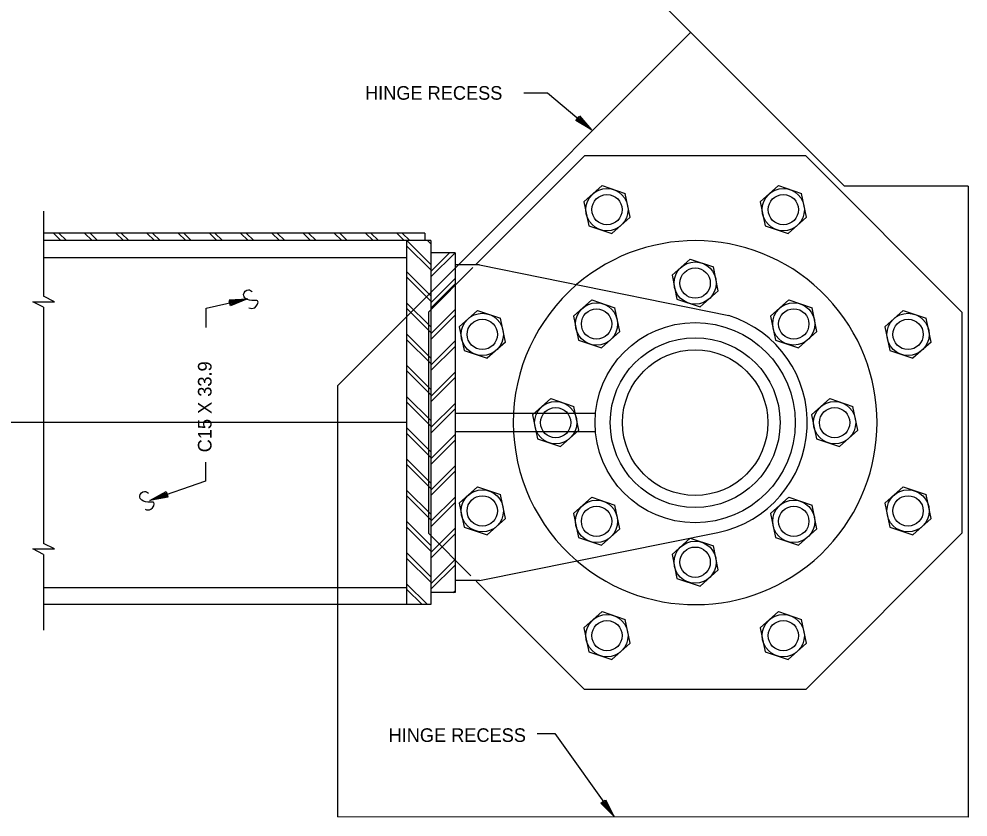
# Model space of a CAD drawing. Extents: x -0.2 to 13.5, y -0.2 to 9.5.
# Drawn here: x 6.602 to 9.863, y 4.919 to 7.66 of the extents above; entities that cross this region are included whole.
import ezdxf

# ---------------------------------------------------------------- set-up
doc = ezdxf.new("R2010")
doc.units = 0
for name, color, linetype in [('Level 13', 7, 'Continuous'), ('Level 2', 7, 'Continuous'), ('Level 25', 7, 'Continuous'), ('Level 3', 7, 'Continuous')]:
    doc.layers.add(name, color=color, linetype=linetype)

msp = doc.modelspace()

# ---------------------------------------------------------------- linework, layer by layer
at = {"layer": 'Level 13'}
for p, q in [((8.5428, 7.0317), (8.6056, 7.0874)), ((8.5428, 7.0317), (8.6056, 7.0874)), ((8.6056, 7.0874), (8.6849, 7.061)), ((8.6056, 7.0874), (8.6849, 7.061)), ((9.1487, 7.0317), (9.2116, 7.0874)), ((9.1487, 7.0317), (9.2116, 7.0874)), ((9.2116, 7.0874), (9.2908, 7.061)), ((9.2116, 7.0874), (9.2908, 7.061)), ((8.7018, 6.9787), (8.6849, 7.061)), ((8.7018, 6.9787), (8.6849, 7.061)), ((9.3077, 6.9787), (9.2908, 7.061)), ((9.3077, 6.9787), (9.2908, 7.061)), ((8.5428, 7.0317), (8.5596, 6.9494)), ((8.5428, 7.0317), (8.5596, 6.9494)), ((9.1487, 7.0317), (9.1656, 6.9494)), ((9.1487, 7.0317), (9.1656, 6.9494)), ((8.7018, 6.9787), (8.6389, 6.923)), ((8.7018, 6.9787), (8.6389, 6.923)), ((9.3077, 6.9787), (9.2448, 6.923)), ((9.3077, 6.9787), (9.2448, 6.923)), ((8.5596, 6.9494), (8.6389, 6.923)), ((8.5596, 6.9494), (8.6389, 6.923)), ((9.1656, 6.9494), (9.2448, 6.923)), ((9.1656, 6.9494), (9.2448, 6.923)), ((8.8458, 6.7795), (8.9086, 6.8352)), ((8.8458, 6.7795), (8.9086, 6.8352)), ((8.9086, 6.8352), (8.9879, 6.8088)), ((8.9086, 6.8352), (8.9879, 6.8088)), ((9.0047, 6.7265), (8.9879, 6.8088)), ((9.0047, 6.7265), (8.9879, 6.8088)), ((8.8458, 6.7795), (8.8626, 6.6972)), ((8.8458, 6.7795), (8.8626, 6.6972)), ((9.0047, 6.7265), (8.9419, 6.6708)), ((9.0047, 6.7265), (8.9419, 6.6708)), ((8.5069, 6.6391), (8.5698, 6.6948)), ((8.5069, 6.6391), (8.5698, 6.6948)), ((8.5698, 6.6948), (8.6491, 6.6684)), ((8.5698, 6.6948), (8.6491, 6.6684)), ((8.8626, 6.6972), (8.9419, 6.6708)), ((8.8626, 6.6972), (8.9419, 6.6708)), ((9.1846, 6.6391), (9.2474, 6.6948)), ((9.1846, 6.6391), (9.2474, 6.6948)), ((9.2474, 6.6948), (9.3267, 6.6684)), ((9.2474, 6.6948), (9.3267, 6.6684)), ((8.1143, 6.6032), (8.1772, 6.659)), ((8.1143, 6.6032), (8.1772, 6.659)), ((8.1772, 6.659), (8.2565, 6.6325)), ((8.1772, 6.659), (8.2565, 6.6325)), ((8.6659, 6.5861), (8.6491, 6.6684)), ((8.6659, 6.5861), (8.6491, 6.6684)), ((9.3436, 6.5861), (9.3267, 6.6684)), ((9.3436, 6.5861), (9.3267, 6.6684)), ((9.5771, 6.6032), (9.64, 6.659)), ((9.5771, 6.6032), (9.64, 6.659)), ((9.64, 6.659), (9.7193, 6.6325)), ((9.64, 6.659), (9.7193, 6.6325)), ((8.2733, 6.5502), (8.2565, 6.6325)), ((8.2733, 6.5502), (8.2565, 6.6325)), ((8.5069, 6.6391), (8.5238, 6.5568)), ((8.5069, 6.6391), (8.5238, 6.5568)), ((9.1846, 6.6391), (9.2014, 6.5569)), ((9.1846, 6.6391), (9.2014, 6.5569)), ((9.7361, 6.5502), (9.7193, 6.6325)), ((9.7361, 6.5502), (9.7193, 6.6325)), ((8.1143, 6.6032), (8.1312, 6.521)), ((8.1143, 6.6032), (8.1312, 6.521)), ((9.5771, 6.6032), (9.594, 6.521)), ((9.5771, 6.6032), (9.594, 6.521)), ((8.5238, 6.5568), (8.6031, 6.5304)), ((8.5238, 6.5568), (8.6031, 6.5304)), ((8.6659, 6.5861), (8.6031, 6.5304)), ((8.6659, 6.5861), (8.6031, 6.5304)), ((9.2014, 6.5569), (9.2807, 6.5304)), ((9.2014, 6.5569), (9.2807, 6.5304)), ((9.3436, 6.5861), (9.2807, 6.5304)), ((9.3436, 6.5861), (9.2807, 6.5304)), ((8.2733, 6.5502), (8.2105, 6.4945)), ((8.2733, 6.5502), (8.2105, 6.4945)), ((9.7361, 6.5502), (9.6733, 6.4945)), ((9.7361, 6.5502), (9.6733, 6.4945)), ((8.1312, 6.521), (8.2105, 6.4945)), ((8.1312, 6.521), (8.2105, 6.4945)), ((9.594, 6.521), (9.6733, 6.4945)), ((9.594, 6.521), (9.6733, 6.4945)), ((8.3666, 6.3003), (8.4294, 6.356)), ((8.3666, 6.3003), (8.4294, 6.356)), ((8.4294, 6.356), (8.5087, 6.3296)), ((8.4294, 6.356), (8.5087, 6.3296)), ((8.5256, 6.2473), (8.5087, 6.3296)), ((8.5256, 6.2473), (8.5087, 6.3296)), ((9.3249, 6.3003), (9.3878, 6.356)), ((9.3249, 6.3003), (9.3878, 6.356)), ((9.3878, 6.356), (9.4671, 6.3296)), ((9.3878, 6.356), (9.4671, 6.3296)), ((9.4839, 6.2473), (9.4671, 6.3296)), ((9.4839, 6.2473), (9.4671, 6.3296)), ((8.3666, 6.3003), (8.3834, 6.218)), ((8.3666, 6.3003), (8.3834, 6.218)), ((9.3249, 6.3003), (9.3418, 6.218)), ((9.3249, 6.3003), (9.3418, 6.218)), ((8.5256, 6.2473), (8.4627, 6.1916)), ((8.5256, 6.2473), (8.4627, 6.1916)), ((9.4839, 6.2473), (9.4211, 6.1916)), ((9.4839, 6.2473), (9.4211, 6.1916)), ((8.3834, 6.218), (8.4627, 6.1916)), ((8.3834, 6.218), (8.4627, 6.1916)), ((9.3418, 6.218), (9.4211, 6.1916)), ((9.3418, 6.218), (9.4211, 6.1916)), ((8.1143, 5.9973), (8.1772, 6.0531)), ((8.1143, 5.9973), (8.1772, 6.0531)), ((8.1772, 6.0531), (8.2565, 6.0266)), ((8.1772, 6.0531), (8.2565, 6.0266)), ((9.5771, 5.9973), (9.64, 6.0531)), ((9.5771, 5.9973), (9.64, 6.0531)), ((9.64, 6.0531), (9.7193, 6.0266)), ((9.64, 6.0531), (9.7193, 6.0266)), ((8.2733, 5.9443), (8.2565, 6.0266)), ((8.2733, 5.9443), (8.2565, 6.0266)), ((8.5069, 5.9615), (8.5698, 6.0172)), ((8.5069, 5.9615), (8.5698, 6.0172)), ((8.5698, 6.0172), (8.6491, 5.9908)), ((8.5698, 6.0172), (8.6491, 5.9908)), ((9.1846, 5.9615), (9.2474, 6.0172)), ((9.1846, 5.9615), (9.2474, 6.0172)), ((9.2474, 6.0172), (9.3267, 5.9908)), ((9.2474, 6.0172), (9.3267, 5.9908)), ((9.7361, 5.9443), (9.7193, 6.0266)), ((9.7361, 5.9443), (9.7193, 6.0266)), ((8.1143, 5.9973), (8.1312, 5.9151)), ((8.1143, 5.9973), (8.1312, 5.9151)), ((8.6659, 5.9085), (8.6491, 5.9908)), ((8.6659, 5.9085), (8.6491, 5.9908)), ((9.3435, 5.9085), (9.3267, 5.9908)), ((9.3435, 5.9085), (9.3267, 5.9908)), ((9.5771, 5.9973), (9.594, 5.9151)), ((9.5771, 5.9973), (9.594, 5.9151)), ((8.2733, 5.9443), (8.2105, 5.8886)), ((8.2733, 5.9443), (8.2105, 5.8886)), ((8.5069, 5.9615), (8.5238, 5.8792)), ((8.5069, 5.9615), (8.5238, 5.8792)), ((9.1846, 5.9615), (9.2014, 5.8792)), ((9.1846, 5.9615), (9.2014, 5.8792)), ((9.7361, 5.9443), (9.6733, 5.8886)), ((9.7361, 5.9443), (9.6733, 5.8886)), ((8.1312, 5.9151), (8.2105, 5.8886)), ((8.1312, 5.9151), (8.2105, 5.8886)), ((8.6659, 5.9085), (8.6031, 5.8528)), ((8.6659, 5.9085), (8.6031, 5.8528)), ((9.3435, 5.9085), (9.2807, 5.8528)), ((9.3435, 5.9085), (9.2807, 5.8528)), ((9.594, 5.9151), (9.6733, 5.8886)), ((9.594, 5.9151), (9.6733, 5.8886)), ((8.5238, 5.8792), (8.6031, 5.8528)), ((8.5238, 5.8792), (8.6031, 5.8528)), ((8.8458, 5.8211), (8.9086, 5.8769)), ((8.8458, 5.8211), (8.9086, 5.8769)), ((8.9086, 5.8769), (8.9879, 5.8504)), ((8.9086, 5.8769), (8.9879, 5.8504)), ((9.2014, 5.8792), (9.2807, 5.8528)), ((9.2014, 5.8792), (9.2807, 5.8528)), ((9.0047, 5.7681), (8.9879, 5.8504)), ((9.0047, 5.7681), (8.9879, 5.8504)), ((8.8458, 5.8211), (8.8626, 5.7389)), ((8.8458, 5.8211), (8.8626, 5.7389)), ((9.0047, 5.7681), (8.9419, 5.7124)), ((9.0047, 5.7681), (8.9419, 5.7124)), ((8.8626, 5.7389), (8.9419, 5.7124)), ((8.8626, 5.7389), (8.9419, 5.7124)), ((8.5428, 5.5689), (8.6056, 5.6246)), ((8.5428, 5.5689), (8.6056, 5.6246)), ((8.6056, 5.6246), (8.6849, 5.5982)), ((8.6056, 5.6246), (8.6849, 5.5982)), ((9.1487, 5.5689), (9.2115, 5.6246)), ((9.1487, 5.5689), (9.2115, 5.6246)), ((9.2115, 5.6246), (9.2908, 5.5982)), ((9.2115, 5.6246), (9.2908, 5.5982)), ((8.7018, 5.5159), (8.6849, 5.5982)), ((8.7018, 5.5159), (8.6849, 5.5982)), ((9.3077, 5.5159), (9.2908, 5.5982)), ((9.3077, 5.5159), (9.2908, 5.5982)), ((8.5428, 5.5689), (8.5596, 5.4866)), ((8.5428, 5.5689), (8.5596, 5.4866)), ((9.1487, 5.5689), (9.1655, 5.4866)), ((9.1487, 5.5689), (9.1655, 5.4866)), ((8.7018, 5.5159), (8.6389, 5.4602)), ((8.7018, 5.5159), (8.6389, 5.4602)), ((9.3077, 5.5159), (9.2448, 5.4602)), ((9.3077, 5.5159), (9.2448, 5.4602)), ((8.5596, 5.4866), (8.6389, 5.4602)), ((8.5596, 5.4866), (8.6389, 5.4602)), ((9.1655, 5.4866), (9.2448, 5.4602)), ((9.1655, 5.4866), (9.2448, 5.4602))]:
    msp.add_line(p, q, dxfattribs=at)
for points in [[(6.6867, 6.6703), (6.6492, 6.6889), (6.7241, 6.6889), (6.6867, 6.7077)], [(6.6867, 5.8214), (6.6492, 5.8401), (6.7241, 5.8401), (6.6867, 5.8588)]]:
    msp.add_lwpolyline(points, dxfattribs=at)
for centre in [(8.6222, 7.005), (8.6222, 7.005), (9.2281, 7.005), (9.2281, 7.005), (8.9252, 6.7528), (8.9252, 6.7528), (8.5864, 6.6124), (8.5864, 6.6124), (9.264, 6.6125), (9.264, 6.6125), (8.1938, 6.5766), (8.1938, 6.5766), (9.6566, 6.5766), (9.6566, 6.5766), (8.446, 6.2736), (8.446, 6.2736), (9.4044, 6.2736), (9.4044, 6.2736), (8.1938, 5.9707), (8.1938, 5.9707), (9.6566, 5.9707), (9.6566, 5.9707), (8.5864, 5.9348), (8.5864, 5.9348), (9.264, 5.9348), (9.264, 5.9348), (8.9252, 5.7945), (8.9252, 5.7945), (8.6222, 5.5422), (8.6222, 5.5422), (9.2281, 5.5422), (9.2281, 5.5422)]:
    msp.add_circle(centre, 0.0725, dxfattribs=at)
at = {"layer": 'Level 2'}
for p, q in [((6.746, 6.8986), (6.72, 6.9247)), ((6.7649, 6.8986), (6.7388, 6.9247)), ((6.8533, 6.8986), (6.8272, 6.9247)), ((6.8721, 6.8986), (6.8461, 6.9247)), ((6.9605, 6.8986), (6.9345, 6.9247)), ((6.9794, 6.8986), (6.9533, 6.9247)), ((7.0678, 6.8986), (7.0417, 6.9247)), ((7.0866, 6.8986), (7.0606, 6.9247)), ((7.175, 6.8986), (7.1489, 6.9247)), ((7.1938, 6.8986), (7.1678, 6.9247)), ((7.2822, 6.8986), (7.2562, 6.9247)), ((7.3011, 6.8986), (7.2751, 6.9247)), ((7.3895, 6.8986), (7.3634, 6.9247)), ((7.4083, 6.8986), (7.3823, 6.9247)), ((7.4967, 6.8986), (7.4707, 6.9247)), ((7.5156, 6.8986), (7.4895, 6.9247)), ((7.604, 6.8986), (7.5779, 6.9247)), ((7.6228, 6.8986), (7.5968, 6.9247)), ((7.7112, 6.8986), (7.6852, 6.9247)), ((7.7301, 6.8986), (7.704, 6.9247)), ((7.8185, 6.8986), (7.7924, 6.9247)), ((7.8373, 6.8986), (7.8113, 6.9247)), ((7.9257, 6.8986), (7.8997, 6.9247)), ((7.9446, 6.8986), (7.9185, 6.9247)), ((8.0171, 6.8168), (7.9337, 6.9001)), ((8.0171, 6.7979), (7.9337, 6.8812)), ((8.0171, 6.8874), (8.0058, 6.8986)), ((8.0171, 6.7739), (8.1001, 6.857)), ((8.0171, 6.7928), (8.0813, 6.857)), ((6.6867, 6.8402), (7.9337, 6.8402)), ((8.0171, 6.7095), (7.9337, 6.7928)), ((8.1004, 6.8041), (8.1004, 6.8041)), ((8.0171, 6.6906), (7.9337, 6.774)), ((8.0171, 6.6855), (8.1004, 6.7688)), ((8.0171, 6.6666), (8.1004, 6.75)), ((8.0171, 6.6023), (7.9337, 6.6856)), ((8.0171, 6.5834), (7.9337, 6.6667)), ((8.0171, 6.5783), (8.1004, 6.6616)), ((8.0171, 6.5594), (8.1004, 6.6427)), ((8.0171, 6.495), (7.9337, 6.5783)), ((8.0171, 6.4762), (7.9337, 6.5595)), ((8.0171, 6.471), (8.1004, 6.5543)), ((8.0171, 6.4522), (8.1004, 6.5355)), ((8.0171, 6.3878), (7.9337, 6.4711)), ((8.0171, 6.3689), (7.9337, 6.4523)), ((8.0171, 6.3638), (8.1004, 6.4471)), ((8.0171, 6.3449), (8.1004, 6.4282)), ((8.0171, 6.2805), (7.9337, 6.3639)), ((8.0171, 6.2617), (7.9337, 6.345)), ((8.0171, 6.2565), (8.1004, 6.3398)), ((8.0171, 6.2377), (8.1004, 6.321)), ((7.9337, 6.2736), (6.0129, 6.2736)), ((8.0171, 6.1733), (7.9337, 6.2566)), ((8.0171, 6.1544), (7.9337, 6.2378)), ((8.0171, 6.1493), (8.1004, 6.2326)), ((8.0171, 6.1304), (8.1004, 6.2137)), ((8.0171, 6.066), (7.9337, 6.1494)), ((8.0171, 6.0472), (7.9337, 6.1305)), ((8.0171, 6.042), (8.1004, 6.1253)), ((8.0171, 6.0232), (8.1004, 6.1065)), ((8.0171, 5.9588), (7.9337, 6.0421)), ((8.0171, 5.9399), (7.9337, 6.0233)), ((8.0171, 5.9348), (8.1004, 6.0181)), ((8.0171, 5.9159), (8.1004, 5.9993)), ((8.0171, 5.8516), (7.9337, 5.9349)), ((8.0171, 5.8327), (7.9337, 5.916)), ((8.0171, 5.8275), (8.1004, 5.9109)), ((8.0171, 5.8087), (8.1004, 5.892)), ((8.0171, 5.7443), (7.9337, 5.8276)), ((8.0171, 5.7254), (7.9337, 5.8088)), ((8.0171, 5.7203), (8.1004, 5.8036)), ((8.0171, 5.7014), (8.1004, 5.7848)), ((6.6867, 5.707), (7.9337, 5.707)), ((8.0055, 5.6486), (7.9337, 5.7204)), ((7.9867, 5.6486), (7.9337, 5.7015)), ((8.0943, 5.6903), (8.1004, 5.6964))]:
    msp.add_line(p, q, dxfattribs=at)
at = {"layer": 'Level 25'}
for p, q in [((8.4318, 8.0929), (9.4385, 7.0861)), ((8.9105, 7.6142), (8.1004, 6.8041)), ((8.5455, 7.1903), (8.1727, 6.8175)), ((8.5455, 7.1903), (8.1727, 6.8175)), ((9.3049, 7.1903), (8.5455, 7.1903)), ((9.3049, 7.1903), (8.5455, 7.1903)), ((9.3049, 7.1903), (9.8419, 6.6533)), ((9.3049, 7.1903), (9.8419, 6.6533)), ((9.8627, 7.0861), (9.4385, 7.0861)), ((9.8627, 7.0861), (9.8627, 4.9194)), ((6.6867, 6.9996), (6.6867, 6.7077)), ((7.9962, 6.9247), (6.6867, 6.9247)), ((7.9962, 6.9247), (6.6867, 6.9247)), ((7.9962, 6.9247), (7.9962, 6.8986)), ((7.9962, 6.9247), (7.9962, 6.8986)), ((8.0171, 6.8986), (6.6867, 6.8986)), ((8.0171, 6.8986), (6.6867, 6.8986)), ((7.9337, 6.8986), (7.9337, 5.6486)), ((8.0171, 6.8986), (8.0171, 5.6486)), ((8.1004, 6.857), (8.0171, 6.857)), ((8.1004, 6.857), (8.0171, 6.857)), ((8.1004, 6.857), (8.1004, 5.6903)), ((8.1004, 6.857), (8.1004, 5.6903)), ((8.1837, 6.8153), (8.1004, 6.8153)), ((8.1837, 6.8153), (8.1004, 6.8153)), ((8.1837, 6.8153), (9.041, 6.6413)), ((8.1837, 6.8153), (9.041, 6.6413)), ((8.1004, 6.8041), (7.696, 6.3998)), ((8.1611, 6.8059), (8.0085, 6.6533)), ((8.1611, 6.8059), (8.0085, 6.6533)), ((6.6867, 6.6703), (6.6867, 5.8588)), ((6.6867, 6.6703), (6.6867, 5.9392)), ((8.0085, 6.6533), (8.0085, 5.894)), ((8.0085, 6.6533), (8.0085, 5.894)), ((8.0085, 6.6533), (8.0085, 5.894)), ((9.8419, 6.6533), (9.8419, 5.8939)), ((9.8419, 6.6533), (9.8419, 5.8939)), ((7.696, 6.3998), (7.696, 5.6486)), ((8.5829, 6.3049), (8.1004, 6.3049)), ((8.5829, 6.3049), (8.1004, 6.3049)), ((8.5829, 6.2424), (8.1004, 6.2424)), ((8.5829, 6.2424), (8.1004, 6.2424)), ((8.0085, 5.8939), (8.1545, 5.7479)), ((8.0085, 5.8939), (8.1545, 5.7479)), ((8.1837, 5.732), (9.0033, 5.8962)), ((8.1837, 5.732), (9.0033, 5.8962)), ((9.8419, 5.8939), (9.3049, 5.357)), ((9.8419, 5.8939), (9.3049, 5.357)), ((6.6867, 5.8214), (6.6867, 5.5605)), ((8.1837, 5.732), (8.1004, 5.732)), ((8.1837, 5.732), (8.1004, 5.732)), ((8.1727, 5.7298), (8.5455, 5.357)), ((8.1727, 5.7298), (8.5455, 5.357)), ((8.1004, 5.6903), (8.0171, 5.6903)), ((8.1004, 5.6903), (8.0171, 5.6903)), ((8.0171, 5.6486), (6.6867, 5.6486)), ((7.696, 5.6486), (7.696, 4.9195)), ((9.3049, 5.357), (8.5455, 5.357)), ((9.3049, 5.357), (8.5455, 5.357)), ((9.8627, 4.9194), (7.696, 4.9195))]:
    msp.add_line(p, q, dxfattribs=at)
for centre, radius in [((8.6222, 7.005), 0.0521), ((8.6222, 7.005), 0.0521), ((9.2281, 7.005), 0.0521), ((9.2281, 7.005), 0.0521), ((8.9252, 6.7528), 0.0521), ((8.9252, 6.7528), 0.0521), ((8.5864, 6.6124), 0.0521), ((8.5864, 6.6124), 0.0521), ((9.264, 6.6125), 0.0521), ((9.264, 6.6125), 0.0521), ((8.1938, 6.5766), 0.0521), ((8.1938, 6.5766), 0.0521), ((9.6566, 6.5766), 0.0521), ((9.6566, 6.5766), 0.0521), ((8.9252, 6.2736), 0.3438), ((8.9252, 6.2736), 0.3438), ((8.9252, 6.2736), 0.2917), ((8.9252, 6.2736), 0.2917), ((8.9252, 6.2736), 0.25), ((8.9252, 6.2736), 0.25), ((8.446, 6.2736), 0.0521), ((8.446, 6.2736), 0.0521), ((9.4044, 6.2736), 0.0521), ((9.4044, 6.2736), 0.0521), ((8.1938, 5.9707), 0.0521), ((8.1938, 5.9707), 0.0521), ((9.6566, 5.9707), 0.0521), ((9.6566, 5.9707), 0.0521), ((8.5864, 5.9348), 0.0521), ((8.5864, 5.9348), 0.0521), ((9.264, 5.9348), 0.0521), ((9.264, 5.9348), 0.0521), ((8.9252, 5.7945), 0.0521), ((8.9252, 5.7945), 0.0521), ((8.6222, 5.5422), 0.0521), ((8.6222, 5.5422), 0.0521), ((9.2281, 5.5422), 0.0521), ((9.2281, 5.5422), 0.0521)]:
    msp.add_circle(centre, radius, dxfattribs=at)
for radius, start, end in [(0.625, 229.4043, 130.6967), (0.625, 130.6967, 229.4043), (0.3854, 281.6931, 72.5189), (0.3854, 281.6931, 72.5189)]:
    msp.add_arc((8.9252, 6.2736), radius, start, end, dxfattribs=at)
for points in [[(7.3919, 6.6683), (7.4118, 6.6683), (7.4218, 6.6916), (7.4102, 6.6933), (7.3802, 6.6999), (7.3736, 6.7133), (7.3902, 6.7299), (7.4035, 6.7232)], [(7.0353, 5.9761), (7.0552, 5.9761), (7.0652, 5.9994), (7.0535, 6.001), (7.0236, 6.0077), (7.017, 6.021), (7.0336, 6.0376), (7.0469, 6.031)]]:
    msp.add_spline(points, degree=3, dxfattribs=at)
at = {"layer": 'Level 3'}
for p, q in [((8.5561, 7.2908), (8.5561, 7.2908)), ((8.5694, 7.2796), (8.5694, 7.2796)), ((7.3699, 6.695), (7.3699, 6.695)), ((7.3868, 6.6989), (7.3868, 6.6989)), ((7.052, 6.0067), (7.052, 6.0067)), ((7.0684, 6.0123), (7.0684, 6.0123)), ((8.6353, 4.936), (8.6353, 4.936)), ((8.6454, 4.9219), (8.6454, 4.9219))]:
    msp.add_line(p, q, dxfattribs=at)
for points in [[(8.3366, 7.4056), (8.4184, 7.4056), (8.5694, 7.2796)], [(8.5281, 7.3275), (8.5694, 7.2796), (8.5149, 7.3116), (8.5262, 7.3252), (8.5561, 7.2908), (8.5191, 7.3125), (8.5263, 7.3212), (8.5433, 7.3014), (8.5232, 7.3133), (8.5262, 7.3169), (8.5299, 7.3125)], [(7.245, 6.6007), (7.245, 6.6662), (7.3868, 6.6989)], [(7.3238, 6.695), (7.3868, 6.6989), (7.3284, 6.6748), (7.3244, 6.6921), (7.3699, 6.695), (7.3303, 6.6787), (7.3277, 6.6897), (7.3537, 6.6913), (7.3321, 6.6825), (7.3311, 6.6871), (7.3368, 6.6874)], [(7.2429, 6.1377), (7.2429, 6.0722), (7.052, 6.0067)], [(7.1143, 6.0172), (7.052, 6.0067), (7.1076, 6.0367), (7.1134, 6.02), (7.0684, 6.0123), (7.1062, 6.0327), (7.1099, 6.022), (7.0842, 6.0177), (7.1048, 6.0287), (7.1063, 6.0243), (7.1006, 6.0234)], [(8.382, 5.2058), (8.4425, 5.2058), (8.6454, 4.9219)], [(8.6175, 4.9786), (8.6454, 4.9219), (8.6007, 4.9666), (8.6151, 4.9768), (8.6353, 4.936), (8.605, 4.9663), (8.6142, 4.9729), (8.6256, 4.9495), (8.6093, 4.9661), (8.613, 4.9688), (8.6155, 4.9636)]]:
    msp.add_lwpolyline(points, dxfattribs=at)

# ---------------------------------------------------------------- texts
at = {"layer": 'Level 2'}
for p in [(7.7909, 7.3825), (7.8718, 5.1773)]:
    msp.add_text('HINGE RECESS', height=0.046698, dxfattribs=at).set_placement(p)
msp.add_text('C15 X 33.9', height=0.0467, rotation=90, dxfattribs=at).set_placement((7.2635, 6.1717))

doc.saveas('drawing.dxf')
